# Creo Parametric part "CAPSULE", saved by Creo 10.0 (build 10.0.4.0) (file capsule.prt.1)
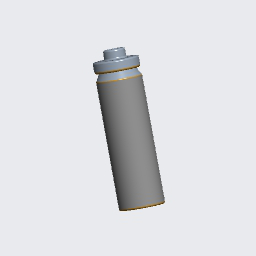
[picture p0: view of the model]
Units: millimeter Kilogram Sec (mmKs); MM, KILOGRAM, SECS

Created from: XX_SOLID_PART_MMKS_NEW_ABS.PRT

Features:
  1. datum plane "RIGHT"
  2. datum plane "TOP"
  3. datum plane "FRONT"
  4. coordinate system
  5. revolve "Revolve 1"
  6. round "Round 1"
  7. shell "Shell 1"

Surfaces: 24 torus, 16 cone, 16 cylinder, 10 plane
